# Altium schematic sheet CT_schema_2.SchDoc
size 454 x 387 mm
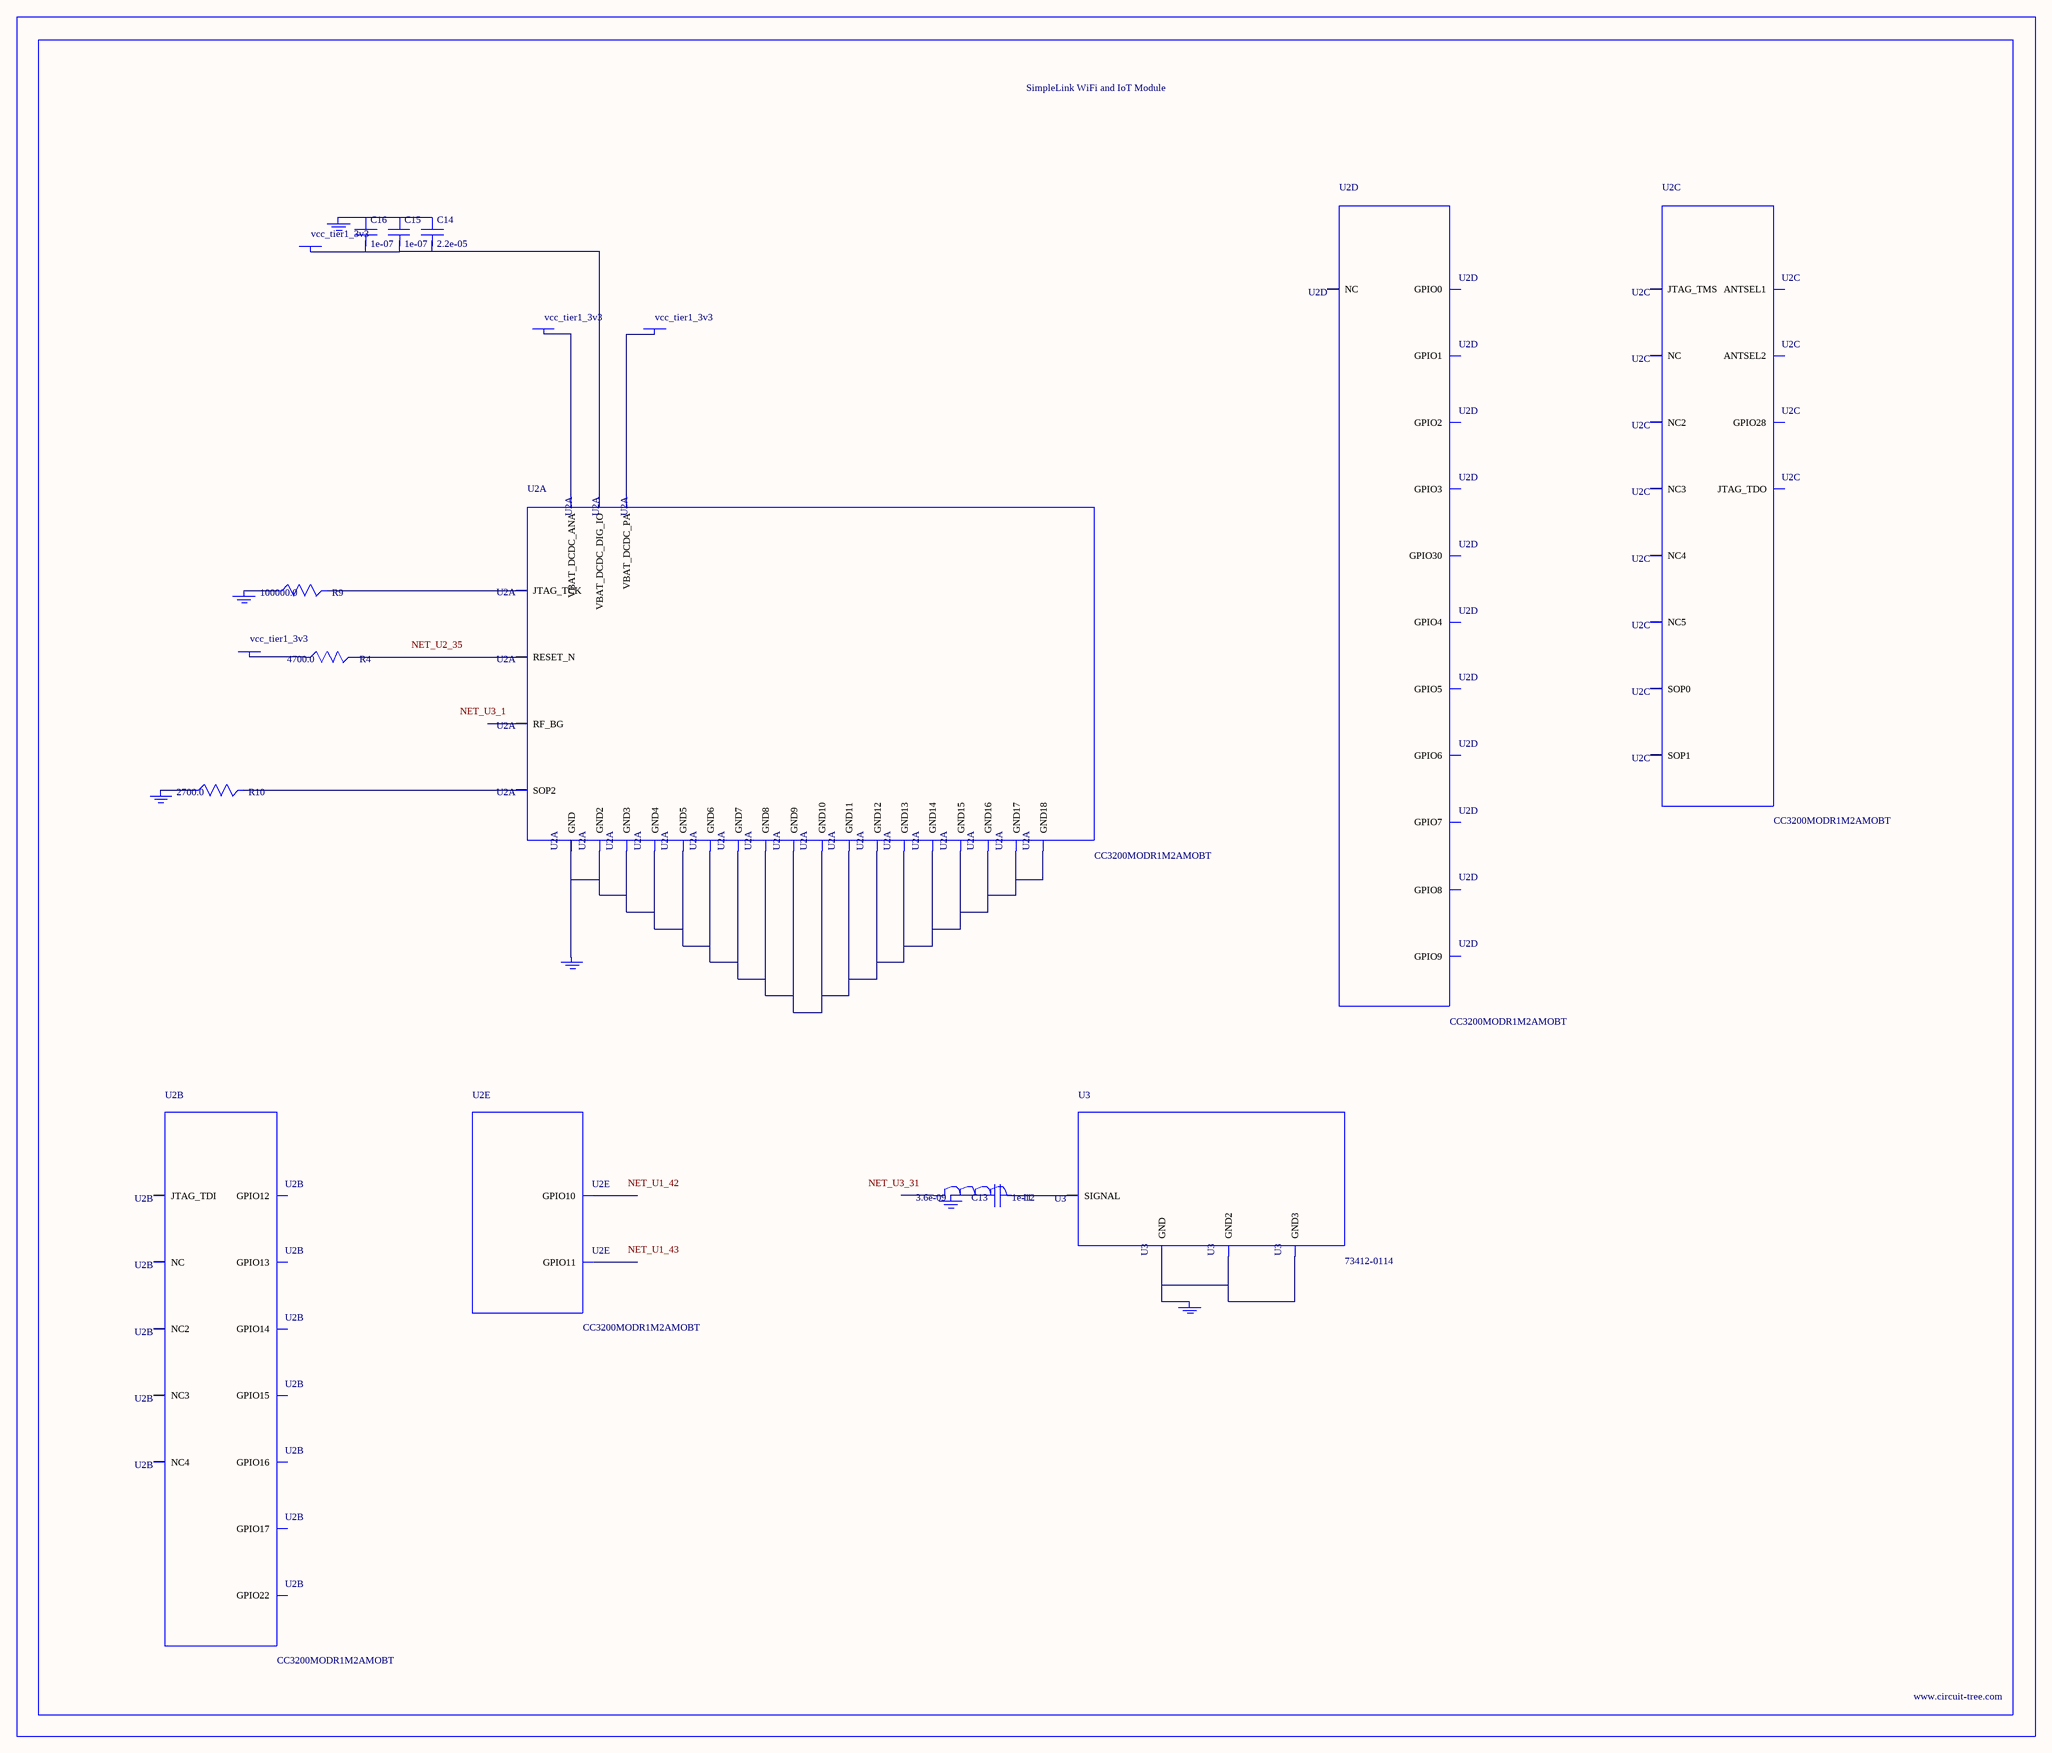
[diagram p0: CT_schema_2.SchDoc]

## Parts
BORDER1  (no value)
C13  1e-12  [C0402]
C14  2.2e-05  [C1210]
C15  1e-07  [C0402]
C16  1e-07  [C0402]
GND_INSTANCE_1_0  (no value)
GND_INSTANCE_1_1  (no value)
GND_INSTANCE_1_2  (no value)
GND_INSTANCE_1_3  (no value)
GND_INSTANCE_1_4  (no value)
GND_INSTANCE_1_5  (no value)
I1  3.6e-09  [C0402]
POWER_INSTANCE_1_0  vcc_tier1_3v3
POWER_INSTANCE_1_1  vcc_tier1_3v3
POWER_INSTANCE_1_2  vcc_tier1_3v3
POWER_INSTANCE_1_3  vcc_tier1_3v3
R4  4700.0  [R0603]
R9  100000.0  [R0603]
R10  2700.0  [R0603]
U2  CC3200MODR1M2AMOBT  [LGA63S127P16X13_2050X1750X150]  (parts A,B,C,D,E of 5)
U3  73412-0114  [COAXIAL_C]

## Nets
NetC13_1: C13.1 I1.2 U3.1(SIGNAL)
NetC13_2: C13.2 GND_INSTANCE_1_4.0(GND)
NetC14_1: C14.1 C15.1 C16.1 GND_INSTANCE_1_2.0(GND)
NetC14_2: C14.2 C15.2 C16.2 POWER_INSTANCE_1_2.0(PWR) U2.40(VBAT_DCDC_DIG_IO)
NetGND_INSTANCE_1_0_0: GND_INSTANCE_1_0.0(GND) R9.1
NetGND_INSTANCE_1_1_0: GND_INSTANCE_1_1.0(GND) R10.1
NetGND_INSTANCE_1_3_0: GND_INSTANCE_1_3.0(GND) U2.1(GND) U2.2(GND2) U2.16(GND3) U2.27(GND4) U2.28(GND5) U2.30(GND6) U2.32(GND7) U2.38(GND8) U2.43(GND9) U2.55(GND10) U2.56(GND11) U2.57(GND12) U2.58(GND13) U2.59(GND14) U2.60(GND15) U2.61(GND16) U2.62(GND17) U2.63(GND18)
NetGND_INSTANCE_1_5_0: GND_INSTANCE_1_5.0(GND) U3.2(GND) U3.3(GND2) U3.4(GND3)
NetPOWER_INSTANCE_1_0_0: POWER_INSTANCE_1_0.0(PWR) U2.36(VBAT_DCDC_ANA)
NetPOWER_INSTANCE_1_1_0: POWER_INSTANCE_1_1.0(PWR) U2.37(VBAT_DCDC_PA)
NetPOWER_INSTANCE_1_3_0: POWER_INSTANCE_1_3.0(PWR) R4.1
NetR4_2: R4.2 U2.35(RESET_N)
NetR9_2: R9.2 U2.21(JTAG_TCK)
NetR10_2: R10.2 U2.23(SOP2)

Not connected (* = marked no-connect by the designer): I1 1; U2 3(GPIO10) 4(GPIO11) 5(GPIO14) 6(GPIO15) 7(GPIO16) 8(GPIO17) 9(GPIO12) 10(GPIO13) 11(GPIO22) 12(JTAG_TDI) 13(NC) 14(NC2) 15(NC3) 17(NC4) 18(JTAG_TDO) 19(GPIO28) 20(NC) 22(JTAG_TMS) 24(SOP1) 25(ANTSEL1) 26(ANTSEL2) 29(NC2) 31(RF_BG) 33(NC3) 34(SOP0) 39(NC4) 41(NC5) 42(GPIO30) 44(GPIO0) 45(NC) 46(GPIO1) 47(GPIO2) 48(GPIO3) 49(GPIO4) 50(GPIO5) 51(GPIO6) 52(GPIO7) 53(GPIO8) 54(GPIO9)

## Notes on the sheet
- Labels drawn without touching a wire or pin: NET_U1_42, NET_U1_43, NET_U2_35, NET_U3_1, NET_U3_31

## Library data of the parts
BORDER1 = BORDER_PAGE1
C13 = C0402C109C3GACTU
C14 = C1210C224K5RACTU
C15 C16 = C0402C104K3RACTU
GND_INSTANCE_1_0-GND_INSTANCE_1_5 = GND
I1 = MCFT0BT3N6
POWER_INSTANCE_1_0-POWER_INSTANCE_1_3 = PWR
R4 = RC0603JR-074K7L
R9 = RC0603JR-07100KL
R10 = RC0603JR-072K7L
